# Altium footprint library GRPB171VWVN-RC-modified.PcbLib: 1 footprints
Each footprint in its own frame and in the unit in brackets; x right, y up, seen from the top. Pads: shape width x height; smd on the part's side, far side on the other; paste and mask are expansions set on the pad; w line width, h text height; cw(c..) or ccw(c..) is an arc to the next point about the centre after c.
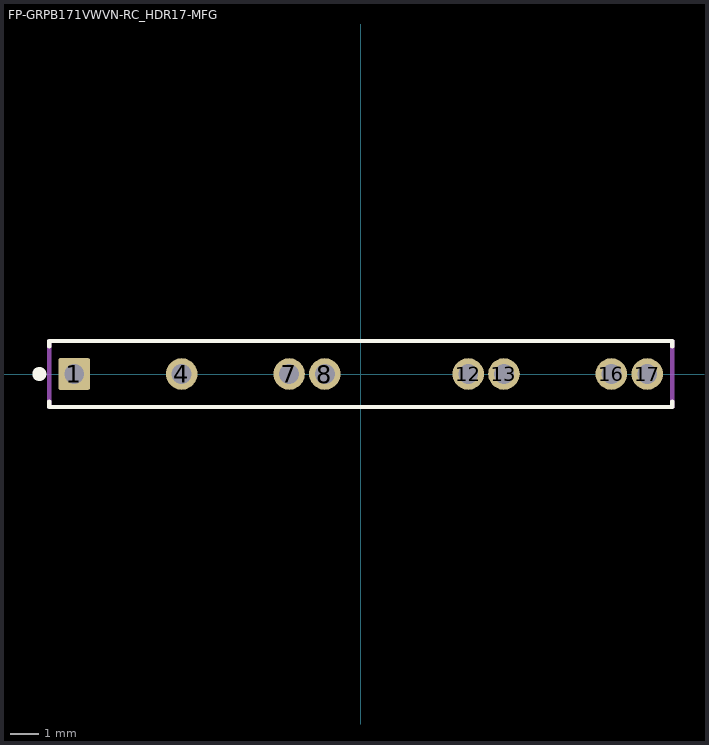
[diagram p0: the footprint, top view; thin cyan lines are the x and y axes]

## FP-GRPB171VWVN-RC_HDR17-MFG [mm]
pads (8):
  rrect9% 1.12x1.12 hole 0.7 paste-1000 mask+0: 1(-10.16,0)
  round 1.12 hole 0.7 paste-1000 mask+0: 4(-6.35,0) 7(-2.54,0) 8(-1.27,0) 12(3.81,0) 13(5.08,0) 16(8.89,0) 17(10.16,0)
Top Overlay:
  circle w0.25: c-11.395,0 r0.125
  lines w0.15: -11.045,-0.975 -11.045,-1.17 11.045,-1.17 11.045,-0.975 ; -11.045,0.975 -11.045,1.17 11.045,1.17 11.045,0.975
Mechanical 5:
  lines w0.15: -11.045,-1.17 11.045,-1.17 11.045,1.17 -11.045,1.17 -11.045,-1.17
  text ".Designator" at 0.05,0.217 h0.5
3D body "Conn_GRPB171VWVN-RC_HDR17.STEP": height 0.25, standoff 0, extent -11.145,-1.27 11.145,1.27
